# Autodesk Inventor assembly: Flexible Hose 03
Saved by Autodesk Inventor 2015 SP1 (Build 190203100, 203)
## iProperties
Created: 2013-02
Part Number: Flexible Hose 03
Document SubType Name: Assembly
Designer: Marci
Name: Hydraulic Hose - No Fittings
ActiveState: True
PipeType: Flexible Hose
Material: UnInitValue
Standard: UnInitValue
FittingMaterial: UnInitValue
FittingStandard: UnInitValue
RouteDirection90: UnInitValue
RouteDirection45: UnInitValue
IsFlanged: UnInitValue
IsButtWelded: UnInitValue
DiameterType: Nominal
Diameter: 1/4
Schedule: ID=0.25
OD: 1,4986
ID: 0,635
Ending: UnInitValue
IntermediateSegmentsMin: UnInitValue
IntermediateSegmentsMax: UnInitValue
IntermediateSegmentsInc: UnInitValue
TerminationSegmentsMin: UnInitValue
TerminationSegmentsMax: UnInitValue
TerminationSegmentsInc: UnInitValue
RoundUpValue: 0.125 in
DefaultBendRadius: UnInitValue
BendRadius: 0.500 in
PipingComponentColor: Blue (Flat)
PipeKey: v3#d489867e-ac9b-47ea-b952-0a1b885f66be#1
CouplingKey: UnInitValue
Elbow90Key: UnInitValue
Elbow45Key: UnInitValue
SuppressStartFitting: True
SuppressEndFitting: True
FlangeKey: UnInitValue
GasketKey: UnInitValue
Gap: UnInitValue
UseSubASM: True
_ComponentInfo: <CS><C N="Pipe" R="0,749300" OR="0,749300" IR="0,317500" PL="PL" PartType="pipe" SymKey="" PN="Parker hidraulikatömlő - No Skive 1/4"><CO N="1"><FE V="0"/><FD V
ShowGap: UnInitValue
MixedUnits: UnInitValue
UseFlangsForCouplings: UnInitValue
IsSelfDraining: UnInitValue
ElbowCustomKey: UnInitValue
Angle: UnInitValue
Author: Marci
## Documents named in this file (3)
- C:\Users\TREINA11\Desktop\#01- Polymechanics and Automation\01 - 3D Models\Pneumatic System\Teljes hajtás.Hose03.iam
- C:\Users\TREINA11\Desktop\#01- Polymechanics and Automation\01 - 3D Models\Pneumatic System\Teljes hajtás.Hose03.ipt
- C:\Users\TREINA11\Desktop\#01- Polymechanics and Automation\01 - 3D Models\Pneumatic System\pifhose.1360342695766.ipt
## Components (2 placed, 2 different names)
1. Hose03
2. Flexible Hose:1
